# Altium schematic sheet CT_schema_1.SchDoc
size 558 x 503 mm
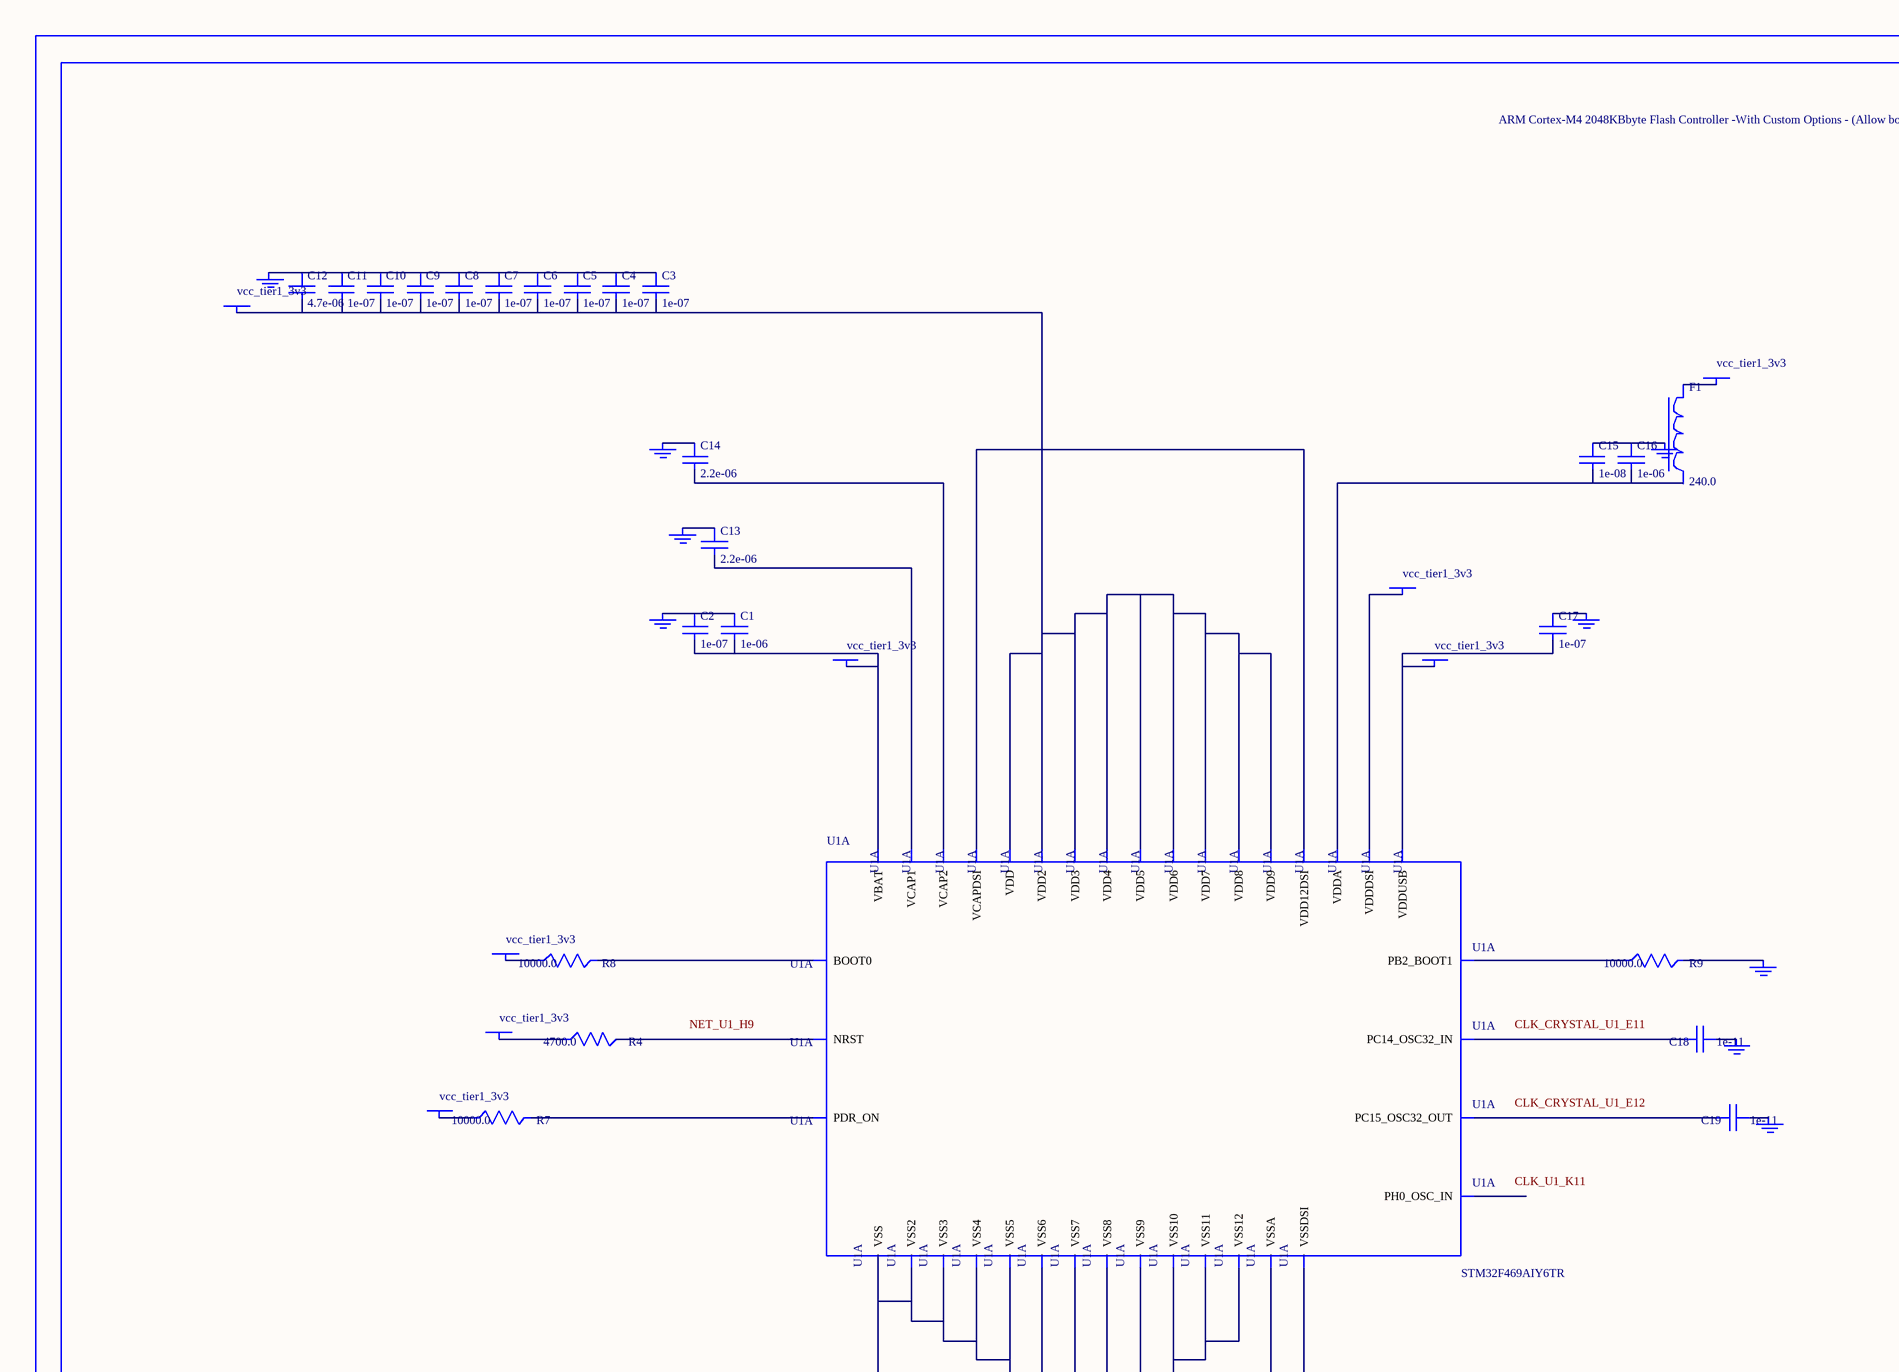
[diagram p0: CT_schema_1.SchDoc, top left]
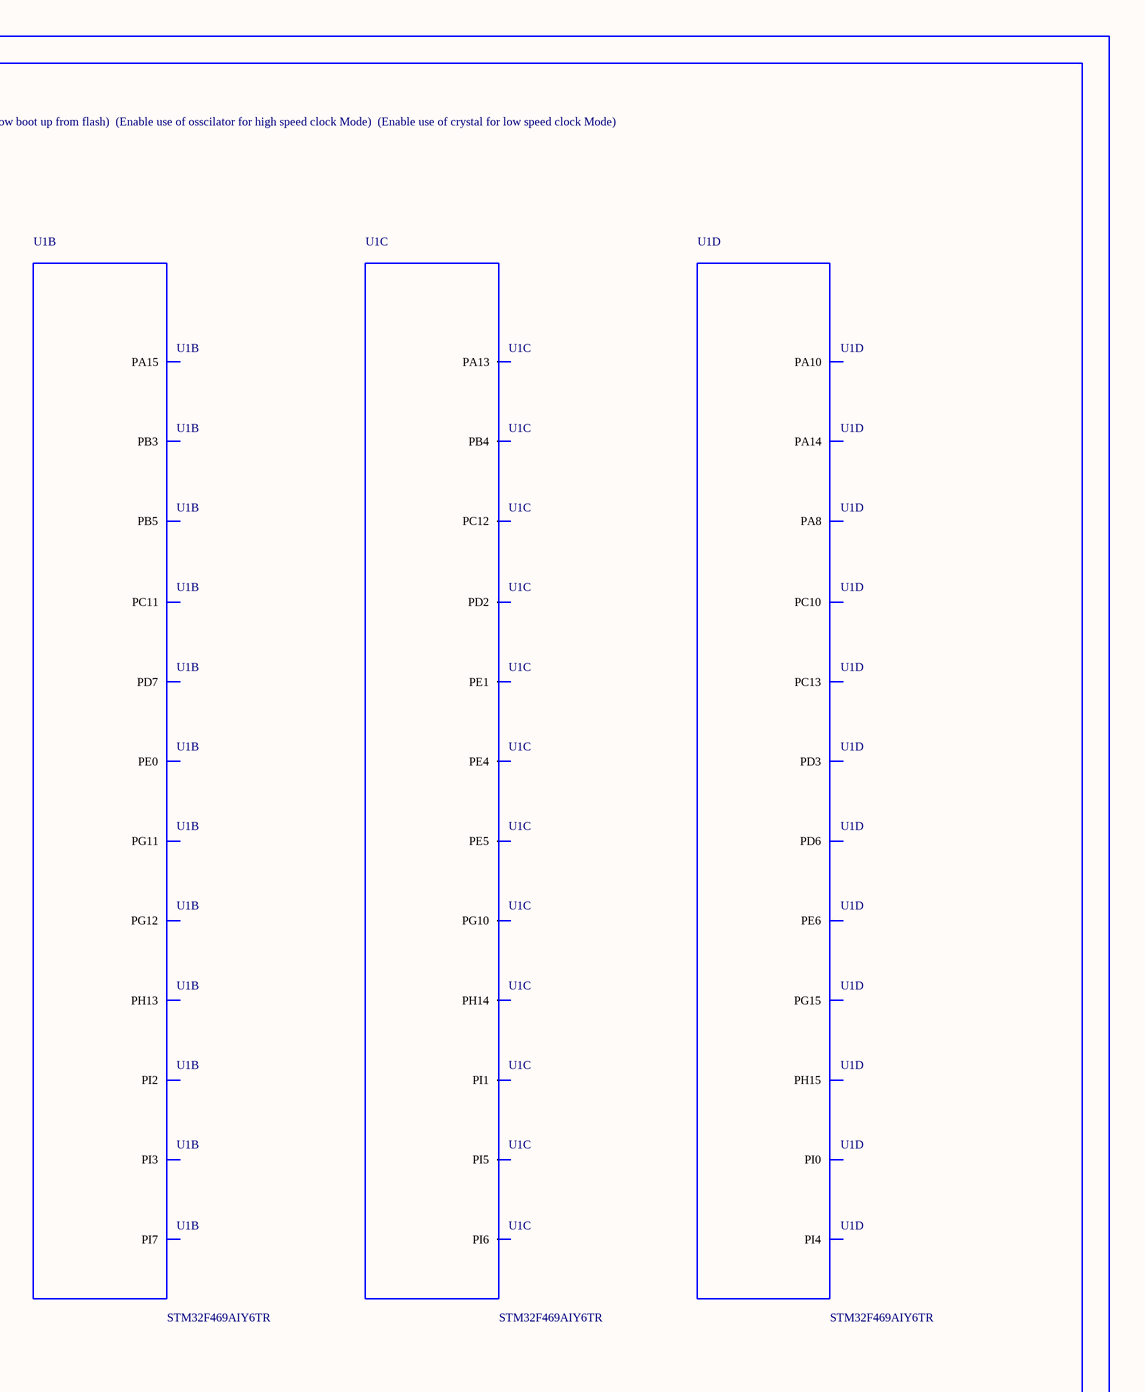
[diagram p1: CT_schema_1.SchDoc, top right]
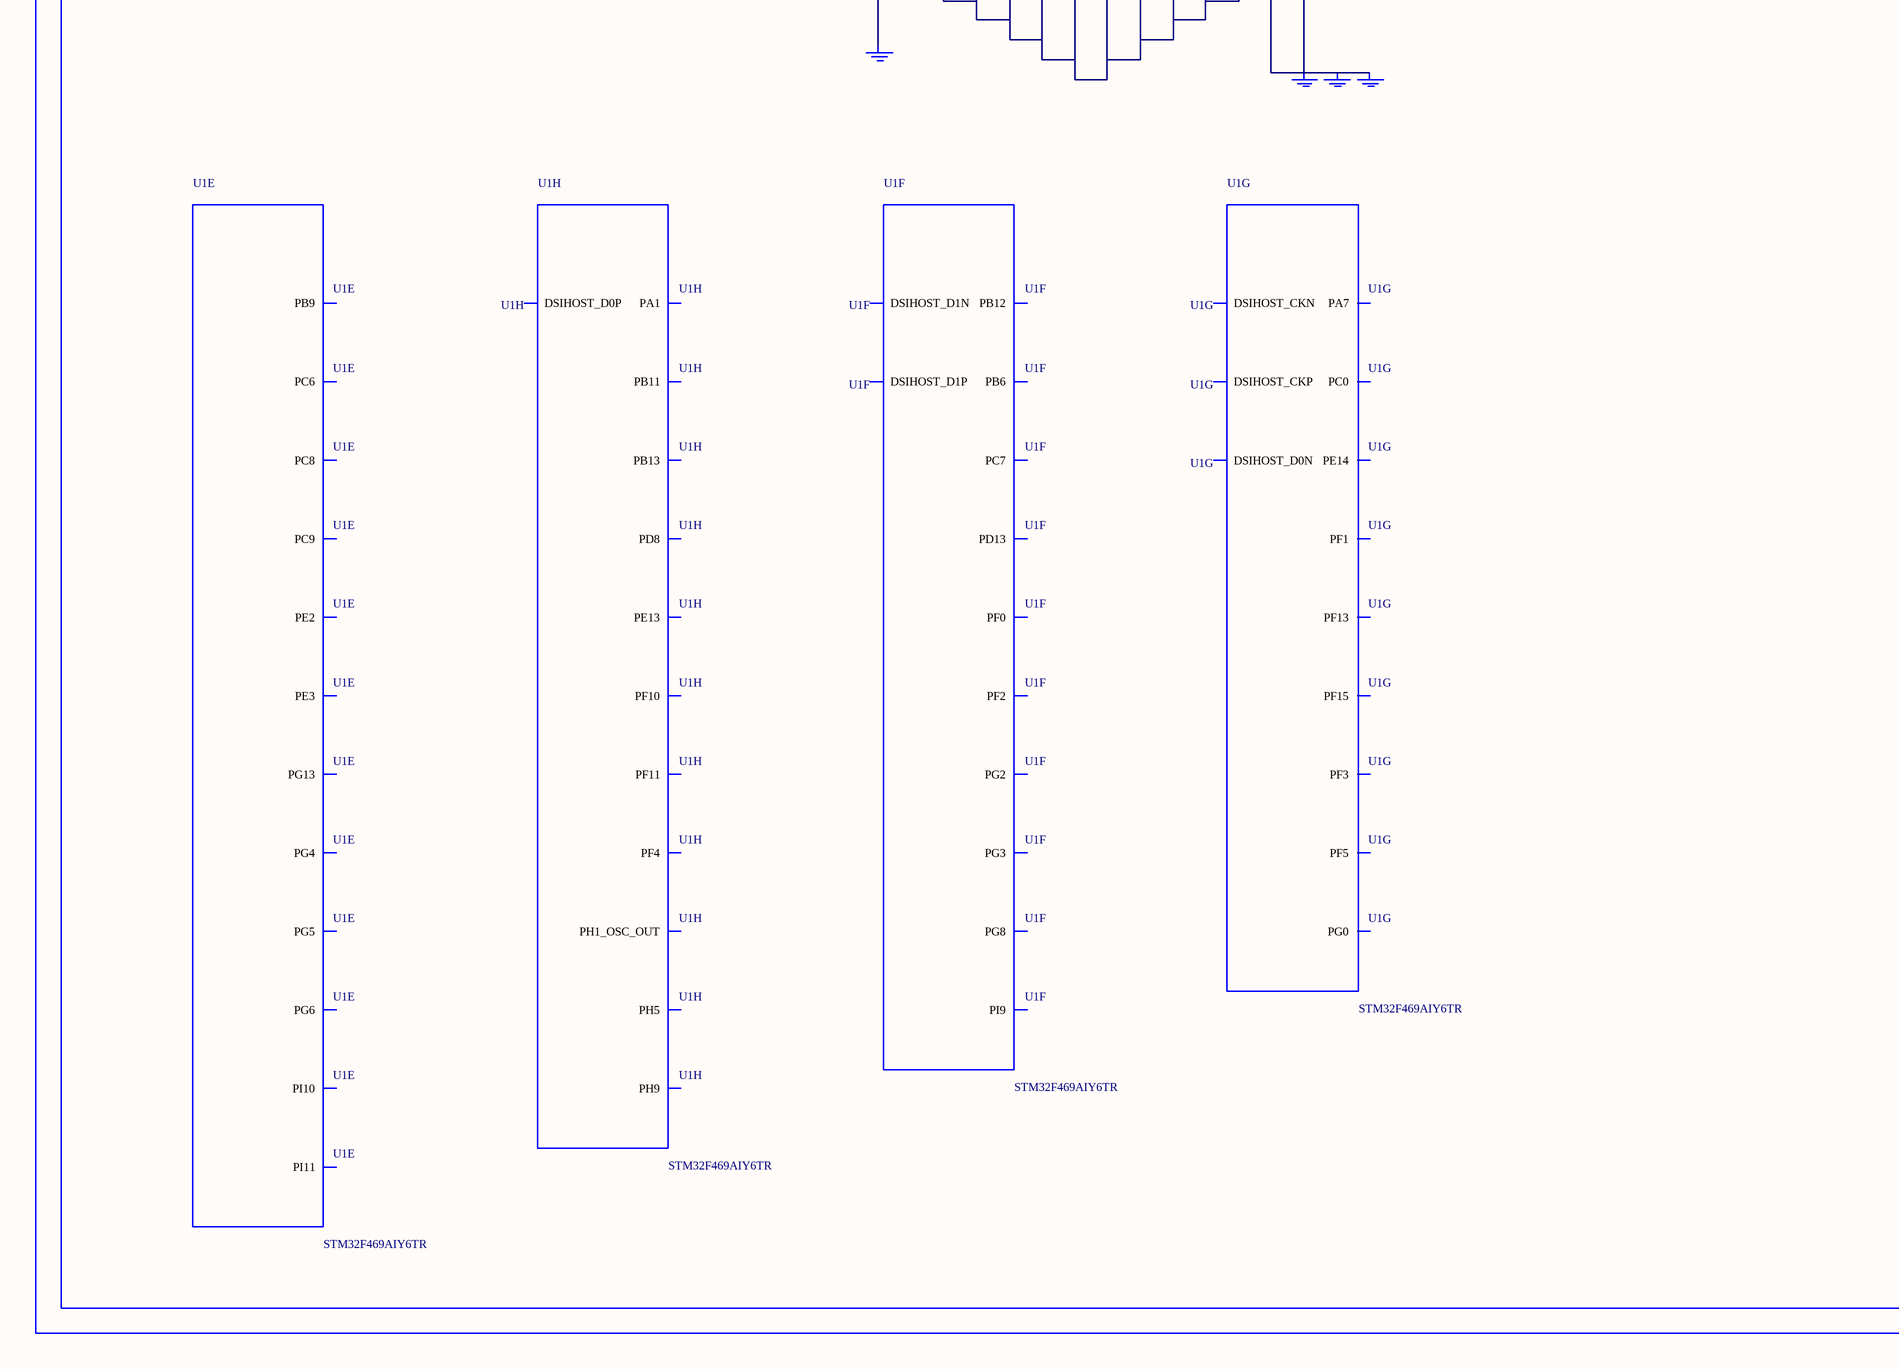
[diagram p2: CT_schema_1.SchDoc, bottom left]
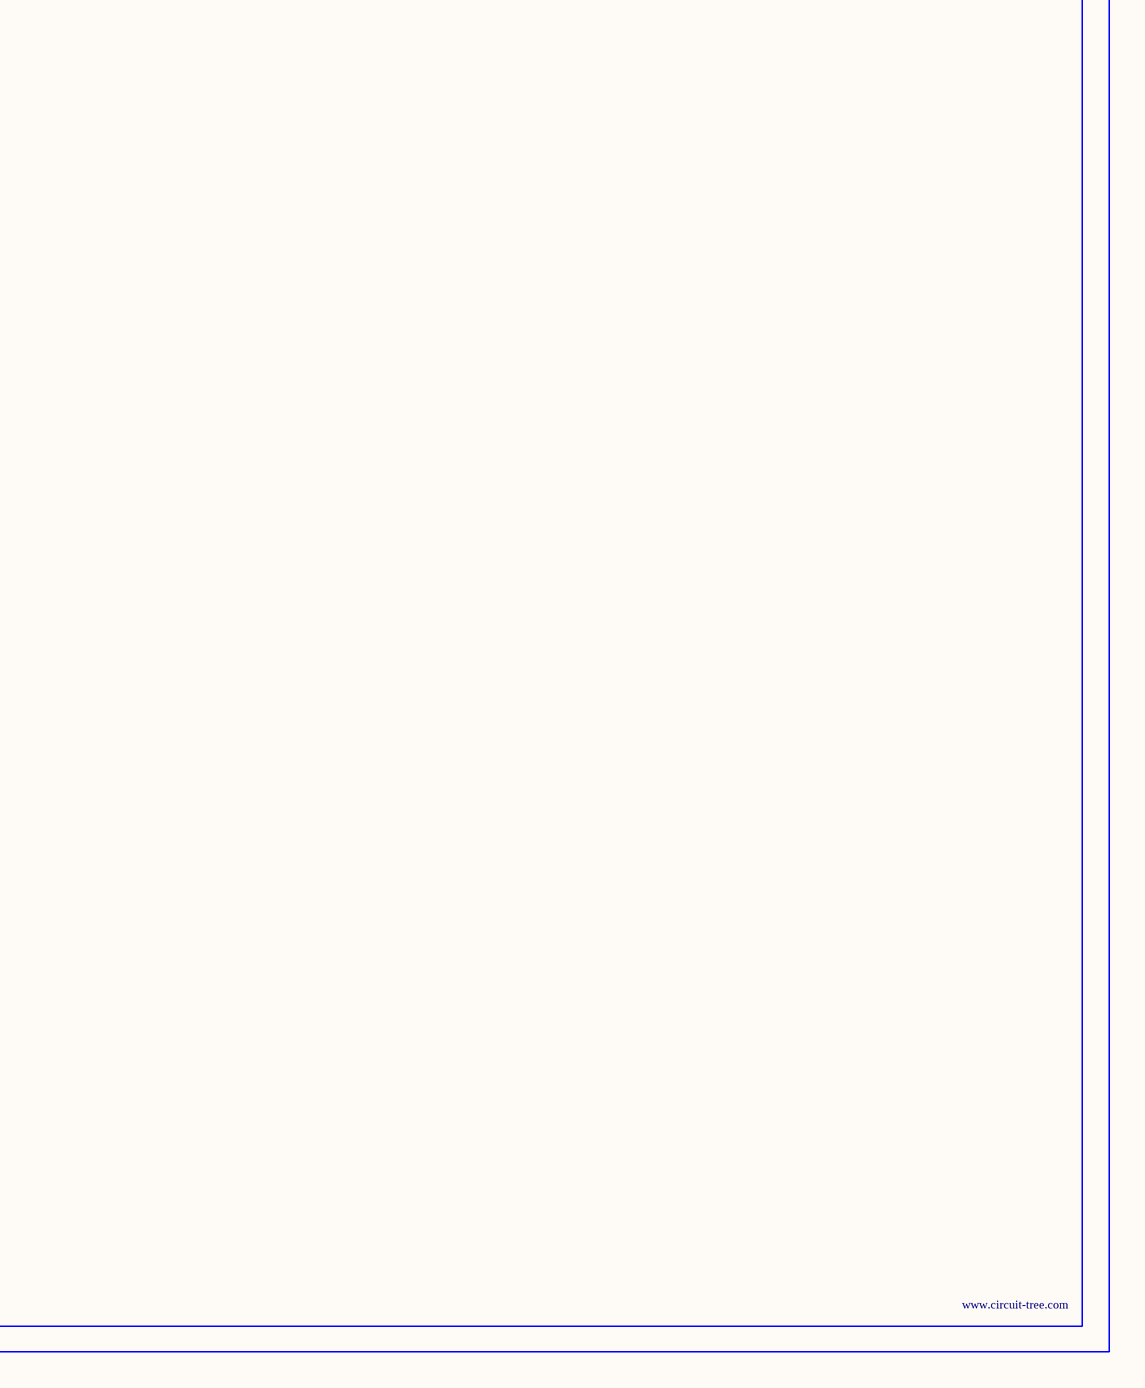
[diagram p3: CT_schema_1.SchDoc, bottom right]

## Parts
BORDER0  (no value)
C1  1e-06  [C0603]
C2  1e-07  [C0603]
C3  1e-07  [C0603]
C4  1e-07  [C0603]
C5  1e-07  [C0603]
C6  1e-07  [C0603]
C7  1e-07  [C0603]
C8  1e-07  [C0603]
C9  1e-07  [C0603]
C10  1e-07  [C0603]
C11  1e-07  [C0603]
C12  4.7e-06  [C0603]
C13  2.2e-06  [C0603]
C14  2.2e-06  [C0603]
C15  1e-08  [C0603]
C16  1e-06  [C0603]
C17  1e-07  [C0603]
C18  1e-11  [C0402]
C19  1e-11  [C0402]
F1  240.0  [L0603]
GND_INSTANCE_0_0  (no value)
GND_INSTANCE_0_1  (no value)
GND_INSTANCE_0_2  (no value)
GND_INSTANCE_0_3  (no value)
GND_INSTANCE_0_4  (no value)
GND_INSTANCE_0_5  (no value)
GND_INSTANCE_0_6  (no value)
GND_INSTANCE_0_7  (no value)
GND_INSTANCE_0_8  (no value)
GND_INSTANCE_0_9  (no value)
GND_INSTANCE_0_10  (no value)
GND_INSTANCE_0_11  (no value)
GND_INSTANCE_0_12  (no value)
POWER_INSTANCE_0_0  vcc_tier1_3v3
POWER_INSTANCE_0_1  vcc_tier1_3v3
POWER_INSTANCE_0_2  vcc_tier1_3v3
POWER_INSTANCE_0_3  vcc_tier1_3v3
POWER_INSTANCE_0_4  vcc_tier1_3v3
POWER_INSTANCE_0_5  vcc_tier1_3v3
POWER_INSTANCE_0_6  vcc_tier1_3v3
POWER_INSTANCE_0_7  vcc_tier1_3v3
R4  4700.0  [R0603]
R7  10000.0  [R0603]
R8  10000.0  [R0603]
R9  10000.0  [R0603]
U1  STM32F469AIY6TR  [WLCSP168]  (parts A,B,C,D,E,F,G,H of 14)

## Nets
NetC1_1: C1.1 C2.1 GND_INSTANCE_0_0.0(GND)
NetC1_2: C1.2 C2.2 POWER_INSTANCE_0_0.0(PWR) U1.C12(VBAT)
NetC3_1: C3.1 C4.1 C5.1 C6.1 C7.1 C8.1 C9.1 C10.1 C11.1 C12.1 GND_INSTANCE_0_2.0(GND)
NetC3_2: C3.2 C4.2 C5.2 C6.2 C7.2 C8.2 C9.2 C10.2 C11.2 C12.2 POWER_INSTANCE_0_2.0(PWR) U1.A7(VDD2) U1.A11(VDD) U1.B5(VDD3) U1.C2(VDD4) U1.G11(VDD5) U1.J12(VDD6) U1.P3(VDD8) U1.P8(VDD9) U1.P12(VDD7)
NetC13_1: C13.1 GND_INSTANCE_0_3.0(GND)
NetC13_2: C13.2 U1.N4(VCAP1)
NetC14_1: C14.1 GND_INSTANCE_0_4.0(GND)
NetC14_2: C14.2 U1.D2(VCAP2)
NetC15_1: C15.1 C16.1 GND_INSTANCE_0_1.0(GND)
NetC15_2: C15.2 C16.2 U1.M12(VDDA)
NetC17_1: C17.1 GND_INSTANCE_0_5.0(GND)
NetC17_2: C17.2 POWER_INSTANCE_0_4.0(PWR) U1.F1(VDDUSB)
NetC18_1: C18.1 GND_INSTANCE_0_7.0(GND)
NetC18_2: C18.2 U1.E11(PC14_OSC32_IN)
NetC19_1: C19.1 GND_INSTANCE_0_8.0(GND)
NetC19_2: C19.2 U1.E12(PC15_OSC32_OUT)
NetF1_1: F1.1 POWER_INSTANCE_0_1.0(PWR)
NetGND_INSTANCE_0_6_0: GND_INSTANCE_0_6.0(GND) R9.2
NetGND_INSTANCE_0_9_0: GND_INSTANCE_0_9.0(GND) GND_INSTANCE_0_10.0(GND) GND_INSTANCE_0_11.0(GND) U1.H1(VSSDSI) U1.L11(VSSA)
NetGND_INSTANCE_0_12_0: GND_INSTANCE_0_12.0(GND) U1.A4(VSS) U1.B7(VSS3) U1.B10(VSS2) U1.C1(VSS4) U1.F2(VSS6) U1.F12(VSS5) U1.H7(VSS7) U1.J11(VSS8) U1.M1(VSS9) U1.N8(VSS11) U1.N11(VSS10) U1.P4(VSS12)
NetPOWER_INSTANCE_0_3_0: POWER_INSTANCE_0_3.0(PWR) R7.1
NetPOWER_INSTANCE_0_5_0: POWER_INSTANCE_0_5.0(PWR) R8.1
NetPOWER_INSTANCE_0_6_0: POWER_INSTANCE_0_6.0(PWR) U1.L1(VDDDSI)
NetPOWER_INSTANCE_0_7_0: POWER_INSTANCE_0_7.0(PWR) R4.1
NetR4_2: R4.2 U1.H9(NRST)
NetR7_2: R7.2 U1.D9(PDR_ON)
NetR8_2: R8.2 U1.F8(BOOT0)
NetR9_1: R9.1 U1.P9(PB2_BOOT1)
NetU1_K1: U1.K1(VCAPDSI) U1.K2(VDD12DSI)

Not connected (* = marked no-connect by the designer): F1 2; U1 A1(PI2) A2(PA15) A5(PD7) A6(PG12) A8(PB3) A10(PE0) A12(PI7) B1(PH13) B2(PI3) B3(PC11) B6(PG11) B8(PB5) B11(PI6) B12(PE5) C3(PI1) C4(PC12) C5(PD2) C7(PG10) C8(PB4) C9(PE1) C10(PI5) C11(PE4) D1(PA13) D3(PH14) D4(PA14) D5(PC10) D6(PD3) D8(PG15) D10(PI4) D11(PE6) D12(PC13) E1(PA8) E3(PA10) E4(PH15) E5(PI0) E7(PD6) E8(PG13) E9(PB9) E10(PE3) F3(PC6) F4(PC8) F5(PC9) F9(PE2) F10(PI10) F11(PI11) G1(PG5) G2(PG4) G3(PG6) G4(PG3) G5(PG2) G6(PG8) G7(PC7) G8(PB6) G9(PI9) G10(PF0) G12(PF2) H2(DSIHOST_D1N) H3(DSIHOST_D1P) H4(PD13) H5(PB12) H8(PF15) H10(PF1) H11(PF3) H12(PF5) J1(DSIHOST_CKP) J2(DSIHOST_CKN) J3(DSIHOST_D0N) J5(PE14) J6(PG0) J7(PF13) J8(PA7) J9(PC0) J10(PF4) K3(DSIHOST_D0P) K4(PB13) K5(PB11) K7(PF11) K8(PH5) K9(PA1) K10(PF10) K11(PH0_OSC_IN) K12(PH1_OSC_OUT) L4(PD8) L5(PH9) L6(PE13)

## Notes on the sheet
- Labels drawn without touching a wire or pin: CLK_CRYSTAL_U1_E11, CLK_CRYSTAL_U1_E12, CLK_U1_K11, NET_U1_H9

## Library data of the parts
BORDER0 = BORDER_PAGE0
C1 C16 = C0603C105K3RACTU
C2-C11 C17 = 06035C104K4Z2A
C12 = GRM188R6YA475KE15D
C13 C14 = C0603C225K8RACTU
C15 = 06035C103K4Z2A
C18 C19 = C0402C100K3GACTU
F1 = Z0603C241ASMST
GND_INSTANCE_0_0-GND_INSTANCE_0_12 = GND
POWER_INSTANCE_0_0-POWER_INSTANCE_0_7 = PWR
R4 = RC0603JR-074K7L
R7-R9 = RC0603JR-0710KL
